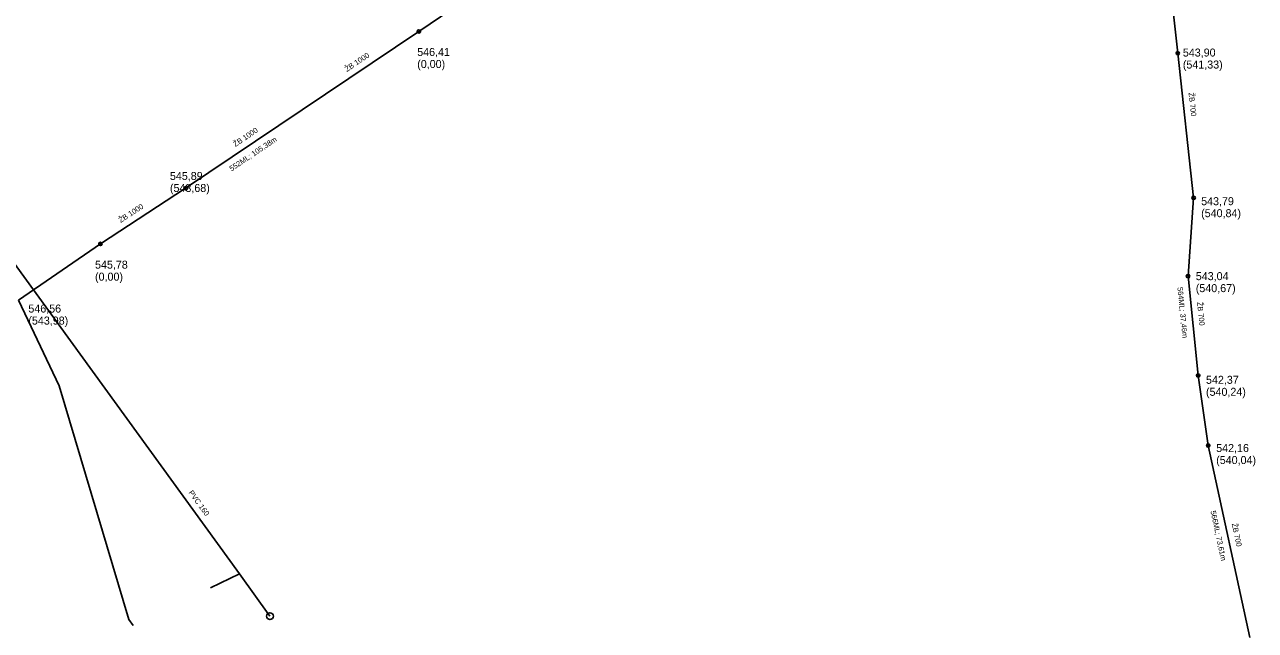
# Model space of a CAD drawing. Extents: x -867696 to -865033, y -1042522 to -1039817.
# Drawn here: x -866337.2 to -865875.8, y -1040519.4 to -1040292.2 of the extents above; entities that cross this region are included whole.
import ezdxf

# ---------------------------------------------------------------- set-up
doc = ezdxf.new("R2010")
doc.units = 0
for name, color, linetype in [('KN - jednotna', 7, 'Continuous'), ('KN - popis material', 7, 'Continuous'), ('KN - popis ostatni', 7, 'Continuous'), ('KN - popis usek delka', 7, 'Continuous'), ('KN - pripojka', 7, 'Continuous'), ('KN - sachta komora', 7, 'Continuous'), ('Level 1', 7, 'Continuous'), ('V - popis material', 7, 'Continuous'), ('V - pripojka', 7, 'Continuous'), ('V - rozvadeci', 7, 'Continuous'), ('V - sachta', 7, 'Continuous')]:
    doc.layers.add(name, color=color, linetype=linetype)

# ---------------------------------------------------------------- blocks, each defined once
blk = doc.blocks.new('100.M')
at = {"layer": 'Level 1'}
blk.add_circle((0, 0), 1.27, dxfattribs=at)
blk = doc.blocks.new('143')
at = {"layer": 'Level 1'}
blk.add_circle((0, 0), 1.27, dxfattribs=at)

msp = doc.modelspace()

# ---------------------------------------------------------------- linework, layer by layer
at = {"layer": 'KN - jednotna'}
for points in [[(-865911.028, -1040247.358), (-865904.917, -1040302.93)], [(-866189.407, -1040294.707), (-866136.097, -1040258.498)], [(-866276.818, -1040353.558), (-866189.407, -1040294.707)], [(-865904.917, -1040302.93), (-865898.957, -1040357.128)], [(-866308.757, -1040374.429), (-866276.818, -1040353.558)], [(-865898.957, -1040357.128), (-865901.067, -1040386.519)], [(-866339.517, -1040395.518), (-866308.757, -1040374.429)], [(-865901.067, -1040386.519), (-865897.258, -1040423.789)], [(-865897.258, -1040423.789), (-865893.469, -1040450.027)], [(-865893.469, -1040450.027), (-865877.948, -1040521.978)]]:
    msp.add_lwpolyline(points, dxfattribs=at)
at = {"layer": 'KN - pripojka'}
msp.add_lwpolyline([(-866339.517, -1040395.518), (-866324.229, -1040427.611), (-866298.12, -1040515.307), (-866296.543, -1040517.515)], dxfattribs=at)
at = {"layer": 'V - pripojka'}
msp.add_lwpolyline([(-866256.693, -1040498.196), (-866267.468, -1040503.349)], dxfattribs=at)
at = {"layer": 'V - rozvadeci'}
msp.add_lwpolyline([(-866434.535, -1040253.041), (-866422.823, -1040269.186), (-866404.632, -1040294.262), (-866256.693, -1040498.196), (-866245.2, -1040514.039)], dxfattribs=at)

# ---------------------------------------------------------------- block references
at = {"layer": 'KN - sachta komora'}
for p, xscale, yscale, rotation in [((-866189.407, -1040294.707), 0.5000000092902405, 0.5000000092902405, -144.99999976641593), ((-865904.917, -1040302.93), 0.500095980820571, 0.500095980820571, 97.08900113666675), ((-866276.818, -1040353.558), 0.4999999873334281, 0.499999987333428, 34.00000045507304), ((-865898.957, -1040357.128), 0.500000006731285, 0.5000000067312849, -88.00000009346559), ((-866308.757, -1040374.429), 0.4999999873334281, 0.499999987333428, -145.99999954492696), ((-865901.067, -1040386.519), 0.5000000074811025, 0.5000000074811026, 90.99999994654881), ((-865897.258, -1040423.789), 0.49999999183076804, 0.49999999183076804, 98.00000038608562), ((-865893.469, -1040450.027), 0.499999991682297, 0.4999999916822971, 101.0000002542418)]:
    msp.add_blockref('100.M', p, dxfattribs=dict(at, xscale=xscale, yscale=yscale, rotation=rotation))
at = {"layer": 'V - sachta', "xscale": 1.000000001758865, "yscale": 1.000000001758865, "rotation": -54.00000066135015}
msp.add_blockref('143', (-866245.2, -1040514.039), dxfattribs=at)

# ---------------------------------------------------------------- texts
at = {"layer": 'KN - popis material'}
for s, rotation, p in [('ŽB 1000', 33.95, (-866216.368, -1040309.966)), ('ŽB 700', 276.28, (-865900.87, -1040317.781)), ('ŽB 1000', 33.95, (-866258.155, -1040338.1)), ('ŽB 1000', 33.16, (-866301.143, -1040366.586)), ('ŽB 700', 275.84, (-865897.657, -1040396.293)), ('ŽB 700', 282.17, (-865884.68, -1040479.386))]:
    msp.add_text(s, height=2, rotation=rotation, dxfattribs=at).set_placement(p)
at = {"layer": 'KN - popis ostatni'}
for s, p in [('546,41 ', (-866190.017, -1040303.947)), ('(0,00)', (-866190.017, -1040308.447)), ('543,90 ', (-865903.007, -1040304.15)), ('(541,33)', (-865903.007, -1040308.65)), ('545,89 ', (-866282.708, -1040350.438)), ('(543,68)', (-866282.708, -1040354.938)), ('543,79 ', (-865896.147, -1040359.898)), ('(540,84)', (-865896.147, -1040364.398)), ('545,78 ', (-866310.787, -1040383.699)), ('(0,00)', (-866310.787, -1040388.199)), ('543,04 ', (-865898.157, -1040388.009)), ('(540,67)', (-865898.157, -1040392.509)), ('546,56 ', (-866335.777, -1040400.168)), ('(543,98)', (-866335.777, -1040404.668)), ('542,37 ', (-865894.328, -1040426.889)), ('(540,24)', (-865894.328, -1040431.389)), ('542,16 ', (-865890.509, -1040452.477)), ('(540,04)', (-865890.509, -1040456.977))]:
    msp.add_text(s, height=3, dxfattribs=at).set_placement(p)
at = {"layer": 'KN - popis usek delka'}
for s, rotation, p in [('552ML; 105,38m', 33.95, (-866259.584, -1040347.259)), ('564ML; 37,46m', 275.84, (-865905.062, -1040390.717)), ('566ML; 73,61m', 282.17, (-865892.656, -1040474.661))]:
    msp.add_text(s, height=1.99999, rotation=rotation, dxfattribs=at).set_placement(p)
at = {"layer": 'V - popis material'}
msp.add_text('PVC 160', height=2, rotation=305.96, dxfattribs=at).set_placement((-866275.839, -1040467.717))

doc.saveas('drawing.dxf')
